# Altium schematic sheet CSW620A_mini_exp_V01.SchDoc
size A4
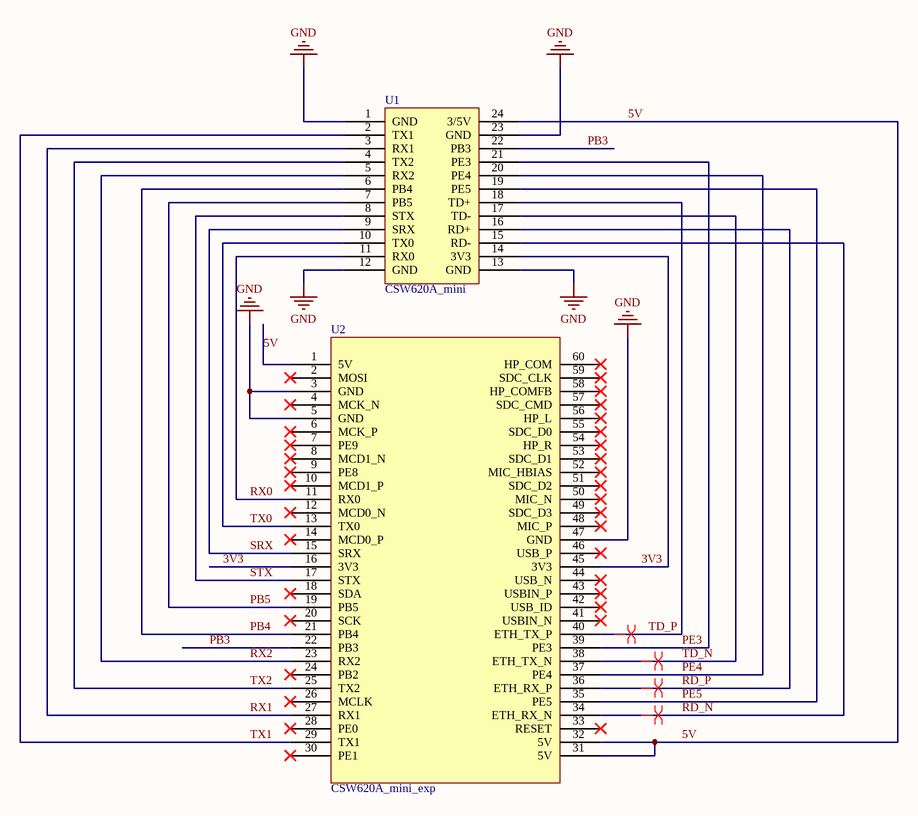
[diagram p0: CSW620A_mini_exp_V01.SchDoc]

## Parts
U1  CSW620A_mini  [CSW620A_MINI]
U2  CSW620A_mini_exp  [CSW520A_V3]

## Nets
GND: U1.1(GND) U1.12(GND) U1.13(GND) U1.23(GND) U2.3(GND) U2.5(GND) U2.47(GND)
3V3: U1.14(3V3) U2.16(3V3) U2.45(3V3)
5V: U1.24(3/5V) U2.1(5V) U2.31(5V) U2.32(5V)
PB3: U1.22(PB3) U2.22(PB3)
PB4: U1.6(PB4) U2.21(PB4)
PB5: U1.7(PB5) U2.19(PB5)
PE3: U1.21(PE3) U2.39(PE3)
PE4: U1.20(PE4) U2.37(PE4)
PE5: U1.19(PE5) U2.35(PE5)
RD_N: U1.15(RD-) U2.34(ETH_RX_N)
RD_P: U1.16(RD+) U2.36(ETH_RX_P)
RX0: U1.11(RX0) U2.11(RX0)
RX1: U1.3(RX1) U2.27(RX1)
RX2: U1.5(RX2) U2.23(RX2)
SRX: U1.9(SRX) U2.15(SRX)
STX: U1.8(STX) U2.17(STX)
TD_N: U1.17(TD-) U2.38(ETH_TX_N)
TD_P: U1.18(TD+) U2.40(ETH_TX_P)
TX0: U1.10(TX0) U2.13(TX0)
TX1: U1.2(TX1) U2.29(TX1)
TX2: U1.4(TX2) U2.25(TX2)

Not connected (* = marked no-connect by the designer): U2 2(MOSI)* 4(MCK_N)* 6(MCK_P)* 7(PE9)* 8(MCD1_N)* 9(PE8)* 10(MCD1_P)* 12(MCD0_N)* 14(MCD0_P)* 18(SDA)* 20(SCK)* 24(PB2)* 26(MCLK)* 28(PE0)* 30(PE1)* 33(RESET)* 41(USBIN_N)* 42(USB_ID)* 43(USBIN_P)* 44(USB_N)* 46(USB_P)* 48(MIC_P)* 49(SDC_D3)* 50(MIC_N)* 51(SDC_D2)* 52(MIC_HBIAS)* 53(SDC_D1)* 54(HP_R)* 55(SDC_D0)* 56(HP_L)* 57(SDC_CMD)* 58(HP_COMFB)* 59(SDC_CLK)* 60(HP_COM)*

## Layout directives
differential pair: RD_N, RD_P, TD_N, TD_P

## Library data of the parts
U2 = CSW620A_mini_expend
